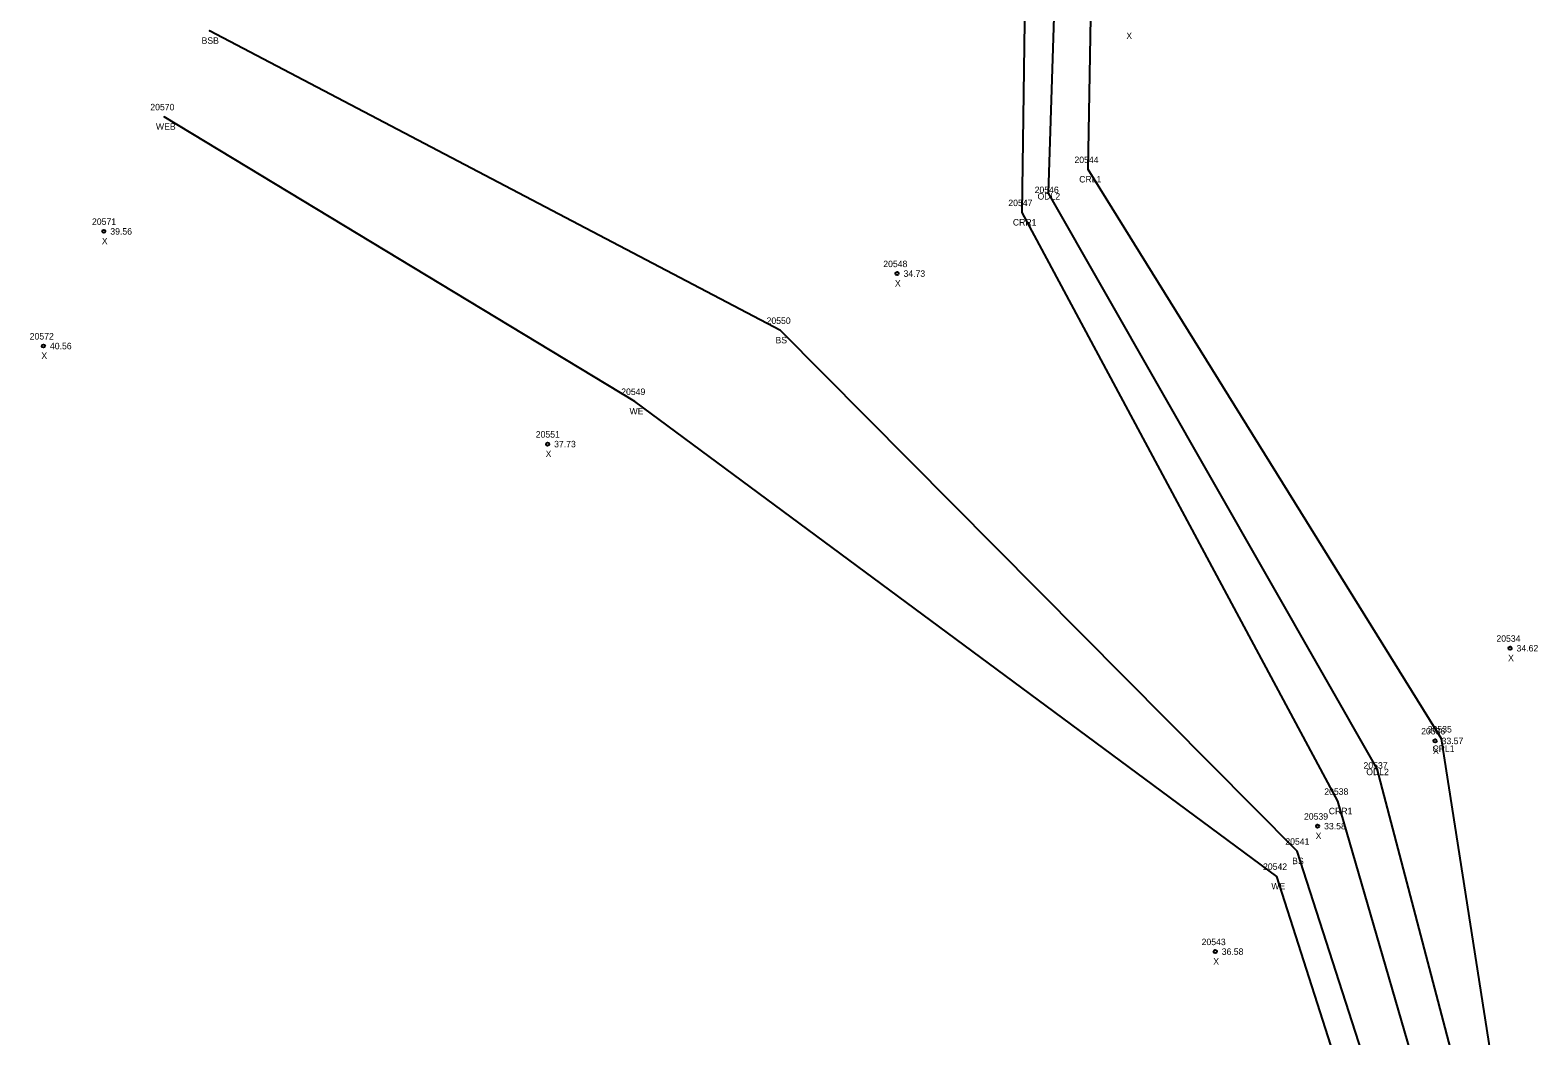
# Model space of a CAD drawing. Extents: x 2445178 to 2446260, y 791158 to 792318.
# Drawn here: x 2445183.5 to 2445416.1, y 791932.6 to 792087.9 of the extents above; entities that cross this region are included whole.
import ezdxf

# ---------------------------------------------------------------- set-up
doc = ezdxf.new("R2010")
doc.units = 0
for name, color, linetype in [('RD_DTM_BkLn2', 7, 'Continuous'), ('RD_EX_H2O', 7, 'Continuous'), ('RD_EX_H2O_txCode', 7, 'Continuous'), ('RD_Sketch8', 7, 'Continuous'), ('RD_SMD_Locator', 7, 'Continuous'), ('RD_SMD_Misc', 7, 'Continuous')]:
    doc.layers.add(name, color=color, linetype=linetype)

msp = doc.modelspace()

# ---------------------------------------------------------------- linework, layer by layer
at = {"layer": 'RD_DTM_BkLn2'}
msp.add_lwpolyline([(2445394.99, 791911.52), (2445379, 791961.15), (2445299.27, 792041.56), (2445211.16, 792087.81)], dxfattribs=at)
at = {"layer": 'RD_EX_H2O'}
for points in [[(2445415.21, 791826.15), (2445411.13, 791915.36), (2445401.26, 791978.48), (2445346.75, 792066.4), (2445347.89, 792130.96), (2445327.72, 792154.04), (2445265.04, 792188.92)], [(2445409.65, 791824.04), (2445406.98, 791914.3), (2445391.36, 791973.89), (2445340.62, 792062.76), (2445342.84, 792131.55), (2445326.53, 792149.18), (2445255.41, 792171.39)], [(2445403.09, 791820.76), (2445401.57, 791912.69), (2445385.3, 791968.86), (2445336.54, 792059.75), (2445337.52, 792129.63), (2445324.7, 792141.79), (2445250.6, 792162.62)], [(2445390.88, 791910.3), (2445375.84, 791957.27), (2445276.8, 792030.59), (2445204.16, 792074.54)]]:
    msp.add_lwpolyline(points, dxfattribs=at)
at = {"layer": 'RD_SMD_Locator'}
for centre, radius in [((2445211.16, 792087.81), 0.001), ((2445204.16, 792074.54), 0.001), ((2445346.75, 792066.4), 0.001), ((2445340.62, 792062.76), 0.001), ((2445336.54, 792059.75), 0.001), ((2445194.83, 792056.85), 0.25), ((2445317.24, 792050.33), 0.25), ((2445299.27, 792041.56), 0.001), ((2445185.51, 792039.15), 0.25), ((2445276.8, 792030.59), 0.001), ((2445263.32, 792024.01), 0.25), ((2445411.86, 791992.49), 0.25), ((2445400.29, 791978.18), 0.25), ((2445401.26, 791978.48), 0.001), ((2445391.36, 791973.89), 0.001), ((2445385.3, 791968.86), 0.001), ((2445382.16, 791965.02), 0.25), ((2445379, 791961.15), 0.001), ((2445375.84, 791957.27), 0.001), ((2445366.36, 791945.65), 0.25)]:
    msp.add_circle(centre, radius, dxfattribs=at)

# ---------------------------------------------------------------- texts
at = {"layer": 'RD_EX_H2O_txCode'}
for s, p in [('20570', (2445202, 792075.54)), ('WEB', (2445202.87, 792072.54)), ('20544', (2445344.63, 792067.4)), ('20546', (2445338.48, 792062.76)), ('CRL1', (2445345.36, 792064.4)), ('20547', (2445334.42, 792060.75)), ('ODL2', (2445338.93, 792061.76)), ('CRR1', (2445335.12, 792057.75)), ('20549', (2445274.68, 792031.59)), ('WE', (2445275.96, 792028.59)), ('20535', (2445399.15, 791979.48)), ('CRL1', (2445399.87, 791976.48)), ('20537', (2445389.24, 791973.89)), ('ODL2', (2445389.66, 791972.89)), ('20538', (2445383.18, 791969.86)), ('CRR1', (2445383.88, 791966.86)), ('20542', (2445373.73, 791958.27)), ('WE', (2445375.01, 791955.27))]:
    msp.add_text(s, height=1, dxfattribs=at).set_placement(p)
at = {"layer": 'RD_Sketch8'}
for s, p in [('X', (2445352.63, 792086.55)), ('20571', (2445193, 792057.85)), ('39.56', (2445195.83, 792056.35)), ('X', (2445194.52, 792054.85)), ('20548', (2445315.12, 792051.33)), ('34.73', (2445318.24, 792049.83)), ('X', (2445316.92, 792048.33)), ('20572', (2445183.39, 792040.15)), ('X', (2445185.19, 792037.15)), ('40.56', (2445186.51, 792038.65)), ('20551', (2445261.49, 792025.01)), ('37.73', (2445264.32, 792023.51)), ('X', (2445263.01, 792022.01)), ('20534', (2445409.75, 791993.49)), ('X', (2445411.55, 791990.49)), ('34.62', (2445412.86, 791991.99)), ('20536', (2445398.14, 791979.18)), ('33.57', (2445401.29, 791977.68)), ('X', (2445399.97, 791976.18)), ('20539', (2445380.05, 791966.02)), ('X', (2445381.85, 791963.02)), ('33.58', (2445383.16, 791964.52)), ('20543', (2445364.25, 791946.65)), ('36.58', (2445367.36, 791945.15)), ('X', (2445366.05, 791943.65))]:
    msp.add_text(s, height=1, dxfattribs=at).set_placement(p)
at = {"layer": 'RD_SMD_Misc'}
for s, p in [('BSB', (2445209.91, 792085.81)), ('20550', (2445297.11, 792042.56)), ('BS', (2445298.49, 792039.56)), ('20541', (2445377.17, 791962.15)), ('BS', (2445378.23, 791959.15))]:
    msp.add_text(s, height=1, dxfattribs=at).set_placement(p)

doc.saveas('drawing.dxf')
